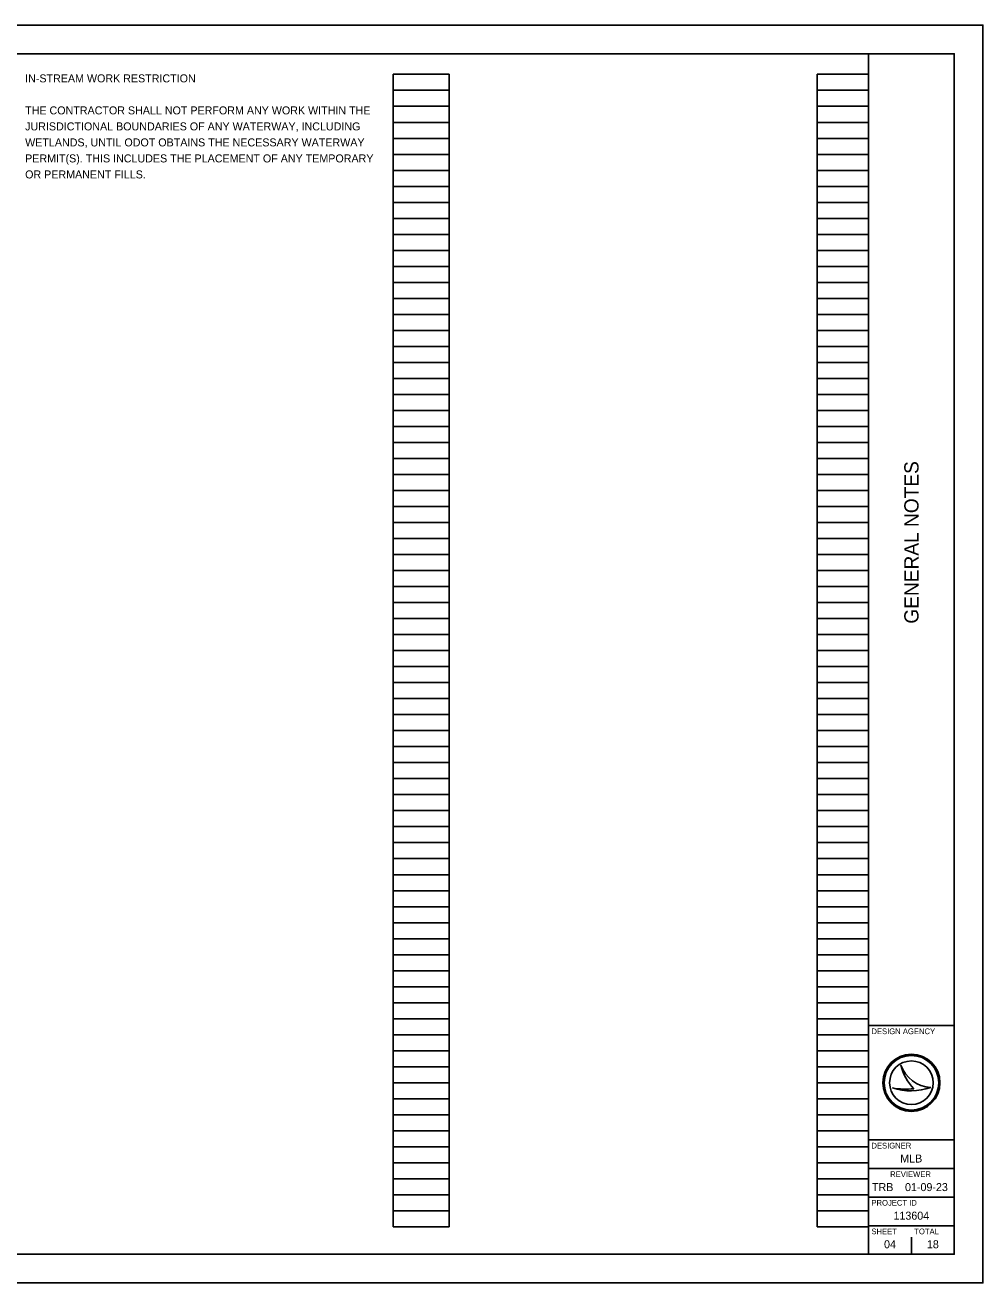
# Model space of a CAD drawing. Extents: x 0 to 34, y 0 to 22.
# Drawn here: x 17.24 to 34, y 0 to 22 of the extents above; entities that cross this region are included whole.
import ezdxf

# ---------------------------------------------------------------- set-up
doc = ezdxf.new("R2010")
doc.units = 0
for name, color, linetype in [('SH_Border', 7, 'Continuous'), ('SH_Cut_Line', 7, 'Continuous'), ('SH_Data', 7, 'Continuous'), ('SH_Text', 7, 'Continuous')]:
    doc.layers.add(name, color=color, linetype=linetype)

msp = doc.modelspace()

# ---------------------------------------------------------------- linework, layer by layer
at = {"layer": 'SH_Border'}
for p, q in [((32, 0.5), (32, 21.5)), ((32, 4.5), (33.5, 4.5)), ((32, 2.5), (33.5, 2.5)), ((32, 2), (33.5, 2)), ((32, 1.5), (33.5, 1.5)), ((32, 1), (33.5, 1))]:
    msp.add_line(p, q, dxfattribs=at)
msp.add_lwpolyline([(1.5, 21.5), (33.5, 21.5), (33.5, 0.5), (1.5, 0.5)], close=True, dxfattribs=at)
at = {"layer": 'SH_Cut_Line'}
msp.add_lwpolyline([(0, 0), (34, 0), (34, 22), (0, 22)], close=True, dxfattribs=at)
at = {"layer": 'SH_Data'}
for p, q in [((23.68, 0.98), (23.68, 21.14)), ((23.68, 21.14), (24.66, 21.14)), ((24.66, 0.98), (24.66, 21.14)), ((31.1, 0.98), (31.1, 21.14)), ((31.1, 21.14), (32, 21.14)), ((32, 0.98), (32, 21.14)), ((23.68, 20.86), (24.66, 20.86)), ((31.1, 20.86), (32, 20.86)), ((23.68, 20.58), (24.66, 20.58)), ((31.1, 20.58), (32, 20.58)), ((23.68, 20.3), (24.66, 20.3)), ((31.1, 20.3), (32, 20.3)), ((23.68, 20.02), (24.66, 20.02)), ((31.1, 20.02), (32, 20.02)), ((23.68, 19.74), (24.66, 19.74)), ((31.1, 19.74), (32, 19.74)), ((23.68, 19.46), (24.66, 19.46)), ((31.1, 19.46), (32, 19.46)), ((23.68, 19.18), (24.66, 19.18)), ((31.1, 19.18), (32, 19.18)), ((23.68, 18.9), (24.66, 18.9)), ((31.1, 18.9), (32, 18.9)), ((23.68, 18.62), (24.66, 18.62)), ((31.1, 18.62), (32, 18.62)), ((23.68, 18.34), (24.66, 18.34)), ((31.1, 18.34), (32, 18.34)), ((23.68, 18.06), (24.66, 18.06)), ((31.1, 18.06), (32, 18.06)), ((23.68, 17.78), (24.66, 17.78)), ((31.1, 17.78), (32, 17.78)), ((23.68, 17.5), (24.66, 17.5)), ((31.1, 17.5), (32, 17.5)), ((23.68, 17.22), (24.66, 17.22)), ((31.1, 17.22), (32, 17.22)), ((23.68, 16.94), (24.66, 16.94)), ((31.1, 16.94), (32, 16.94)), ((23.68, 16.66), (24.66, 16.66)), ((31.1, 16.66), (32, 16.66)), ((23.68, 16.38), (24.66, 16.38)), ((31.1, 16.38), (32, 16.38)), ((23.68, 16.1), (24.66, 16.1)), ((31.1, 16.1), (32, 16.1)), ((23.68, 15.82), (24.66, 15.82)), ((31.1, 15.82), (32, 15.82)), ((23.68, 15.54), (24.66, 15.54)), ((31.1, 15.54), (32, 15.54)), ((23.68, 15.26), (24.66, 15.26)), ((31.1, 15.26), (32, 15.26)), ((23.68, 14.98), (24.66, 14.98)), ((31.1, 14.98), (32, 14.98)), ((23.68, 14.7), (24.66, 14.7)), ((31.1, 14.7), (32, 14.7)), ((23.68, 14.42), (24.66, 14.42)), ((31.1, 14.42), (32, 14.42)), ((23.68, 14.14), (24.66, 14.14)), ((31.1, 14.14), (32, 14.14)), ((23.68, 13.86), (24.66, 13.86)), ((31.1, 13.86), (32, 13.86)), ((23.68, 13.58), (24.66, 13.58)), ((31.1, 13.58), (32, 13.58)), ((23.68, 13.3), (24.66, 13.3)), ((31.1, 13.3), (32, 13.3)), ((23.68, 13.02), (24.66, 13.02)), ((31.1, 13.02), (32, 13.02)), ((23.68, 12.74), (24.66, 12.74)), ((31.1, 12.74), (32, 12.74)), ((23.68, 12.46), (24.66, 12.46)), ((31.1, 12.46), (32, 12.46)), ((23.68, 12.18), (24.66, 12.18)), ((31.1, 12.18), (32, 12.18)), ((23.68, 11.9), (24.66, 11.9)), ((31.1, 11.9), (32, 11.9)), ((23.68, 11.62), (24.66, 11.62)), ((31.1, 11.62), (32, 11.62)), ((23.68, 11.34), (24.66, 11.34)), ((31.1, 11.34), (32, 11.34)), ((23.68, 11.06), (24.66, 11.06)), ((31.1, 11.06), (32, 11.06)), ((23.68, 10.78), (24.66, 10.78)), ((31.1, 10.78), (32, 10.78)), ((23.68, 10.5), (24.66, 10.5)), ((31.1, 10.5), (32, 10.5)), ((23.68, 10.22), (24.66, 10.22)), ((31.1, 10.22), (32, 10.22)), ((23.68, 9.94), (24.66, 9.94)), ((31.1, 9.94), (32, 9.94)), ((23.68, 9.66), (24.66, 9.66)), ((31.1, 9.66), (32, 9.66)), ((23.68, 9.38), (24.66, 9.38)), ((31.1, 9.38), (32, 9.38)), ((23.68, 9.1), (24.66, 9.1)), ((31.1, 9.1), (32, 9.1)), ((23.68, 8.82), (24.66, 8.82)), ((31.1, 8.82), (32, 8.82)), ((23.68, 8.54), (24.66, 8.54)), ((31.1, 8.54), (32, 8.54)), ((23.68, 8.26), (24.66, 8.26)), ((31.1, 8.26), (32, 8.26)), ((23.68, 7.98), (24.66, 7.98)), ((31.1, 7.98), (32, 7.98)), ((23.68, 7.7), (24.66, 7.7)), ((31.1, 7.7), (32, 7.7)), ((23.68, 7.42), (24.66, 7.42)), ((31.1, 7.42), (32, 7.42)), ((23.68, 7.14), (24.66, 7.14)), ((31.1, 7.14), (32, 7.14)), ((23.68, 6.86), (24.66, 6.86)), ((31.1, 6.86), (32, 6.86)), ((23.68, 6.58), (24.66, 6.58)), ((31.1, 6.58), (32, 6.58)), ((23.68, 6.3), (24.66, 6.3)), ((31.1, 6.3), (32, 6.3)), ((23.68, 6.02), (24.66, 6.02)), ((31.1, 6.02), (32, 6.02)), ((23.68, 5.74), (24.66, 5.74)), ((31.1, 5.74), (32, 5.74)), ((23.68, 5.46), (24.66, 5.46)), ((31.1, 5.46), (32, 5.46)), ((23.68, 5.18), (24.66, 5.18)), ((31.1, 5.18), (32, 5.18)), ((23.68, 4.9), (24.66, 4.9)), ((31.1, 4.9), (32, 4.9)), ((23.68, 4.62), (24.66, 4.62)), ((31.1, 4.62), (32, 4.62)), ((23.68, 4.34), (24.66, 4.34)), ((31.1, 4.34), (32, 4.34)), ((23.68, 4.06), (24.66, 4.06)), ((31.1, 4.06), (32, 4.06)), ((23.68, 3.78), (24.66, 3.78)), ((31.1, 3.78), (32, 3.78)), ((32.567, 3.81), (32.567, 3.81)), ((23.68, 3.5), (24.66, 3.5)), ((31.1, 3.5), (32, 3.5)), ((32.417, 3.41), (32.417, 3.41)), ((32.75, 3.5), (32.75, 3.5)), ((33.087, 3.419), (33.087, 3.419)), ((23.68, 3.22), (24.66, 3.22)), ((31.1, 3.22), (32, 3.22)), ((23.68, 2.94), (24.66, 2.94)), ((31.1, 2.94), (32, 2.94)), ((23.68, 2.66), (24.66, 2.66)), ((31.1, 2.66), (32, 2.66)), ((23.68, 2.38), (24.66, 2.38)), ((31.1, 2.38), (32, 2.38)), ((23.68, 2.1), (24.66, 2.1)), ((31.1, 2.1), (32, 2.1)), ((23.68, 1.82), (24.66, 1.82)), ((31.1, 1.82), (32, 1.82)), ((23.68, 1.54), (24.66, 1.54)), ((31.1, 1.54), (32, 1.54)), ((23.68, 1.26), (24.66, 1.26)), ((31.1, 1.26), (32, 1.26)), ((23.68, 0.98), (24.66, 0.98)), ((31.1, 0.98), (32, 0.98)), ((32.375, 0.675), (32.375, 0.675)), ((32.75, 0.5), (32.75, 0.8))]:
    msp.add_line(p, q, dxfattribs=at)
for radius in [0.5, 0.477, 0.477, 0.382]:
    msp.add_circle((32.75, 3.5), radius, dxfattribs=at)
for centre, radius, start, end in [((33.116, 3.998), 0.58, 198.9257, 198.9319), ((33.347, 3.97), 0.796, 191.6379, 191.6421), ((33.116, 3.998), 0.58, 198.9319, 267.1657), ((33.347, 3.97), 0.796, 191.6421, 226.0947), ((32.739, 4.37), 1.013, 251.4576, 290.0832), ((32.648, 4.654), 1.266, 259.4964, 259.4995), ((32.739, 4.37), 1.013, 251.4527, 251.4576), ((32.648, 4.654), 1.266, 259.4995, 276.6672)]:
    msp.add_arc(centre, radius, start, end, dxfattribs=at)

# ---------------------------------------------------------------- texts
msp.add_text('GENERAL NOTES', height=0.25, rotation=90, dxfattribs=at).set_placement((32.875, 11.531))
for s, height, p in [('DESIGN AGENCY', 0.1, (32.05, 4.35)), ('DESIGNER', 0.1, (32.05, 2.35)), ('MLB', 0.14, (32.554, 2.105)), ('REVIEWER', 0.1, (32.378, 1.85)), ('TRB', 0.14, (32.06, 1.605)), ('01-09-23', 0.14, (32.638, 1.605)), ('PROJECT ID', 0.1, (32.05, 1.35)), ('113604', 0.14, (32.436, 1.105)), ('SHEET', 0.1, (32.05, 0.85)), ('TOTAL', 0.1, (32.8, 0.85)), ('04', 0.14, (32.271, 0.605)), ('18', 0.14, (33.021, 0.605))]:
    msp.add_text(s, height=height, dxfattribs=at).set_placement(p)
at = {"layer": 'SH_Text'}
for s, p in [('IN-STREAM WORK RESTRICTION', (17.241, 20.999)), ('THE CONTRACTOR SHALL NOT PERFORM ANY WORK WITHIN THE', (17.241, 20.439)), ('JURISDICTIONAL BOUNDARIES OF ANY WATERWAY, INCLUDING ', (17.241, 20.159)), ('WETLANDS, UNTIL ODOT OBTAINS THE NECESSARY WATERWAY', (17.241, 19.879)), ('PERMIT(S). THIS INCLUDES THE PLACEMENT OF ANY TEMPORARY', (17.241, 19.599)), ('OR PERMANENT FILLS.', (17.241, 19.319))]:
    msp.add_text(s, height=0.14, dxfattribs=at).set_placement(p)

doc.saveas('drawing.dxf')
